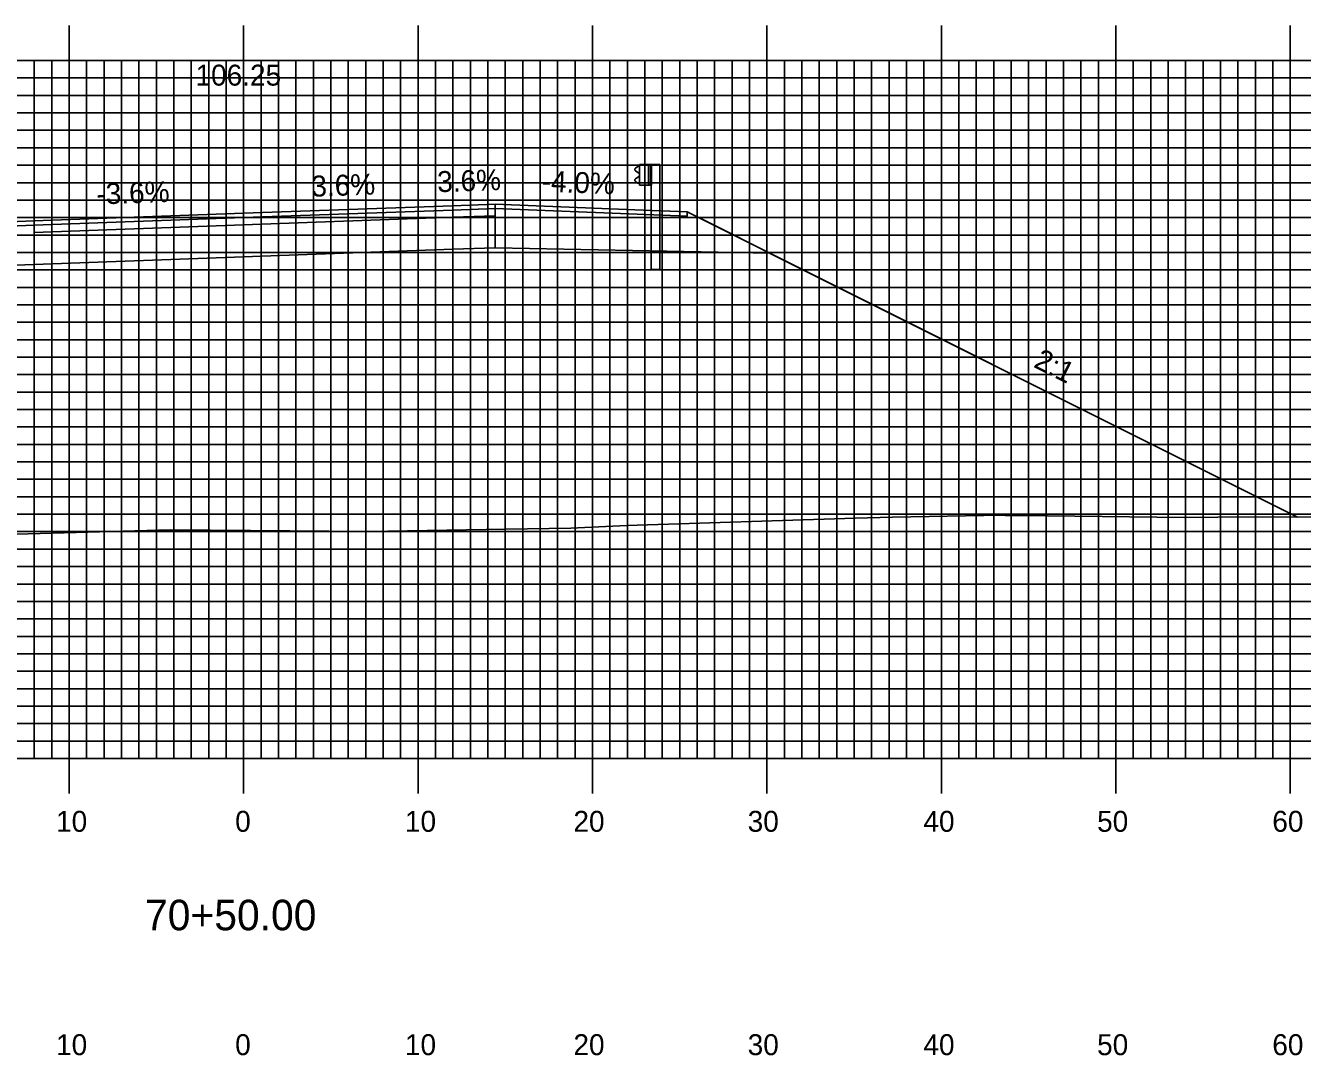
# Model space of a CAD drawing. Extents: x 1760217 to 1760560, y 442591 to 442811.
# Drawn here: x 1760370.2 to 1760443.4, y 442651.6 to 442710.7 of the extents above; entities that cross this region are included whole.
import ezdxf

# ---------------------------------------------------------------- set-up
doc = ezdxf.new("R2010")
doc.units = 0
for name, color, linetype in [('ANNOTATION', 7, 'Continuous'), ('D_Guardrail_Beam_Rt', 7, 'Continuous'), ('D_Roadway_Centerline', 7, 'Continuous'), ('D_Roadway_Centerline_Text', 7, 'Continuous'), ('D_Roadway_Edge_Shoulder', 7, 'Continuous'), ('D_Roadway_Edge_TW', 7, 'Continuous'), ('D_Roadway_Pavement', 7, 'Continuous'), ('D_Roadway_SlopeLines', 7, 'Continuous'), ('D_Roadway_SubGrade', 7, 'Continuous'), ('H_V ANNOTATION', 7, 'Continuous'), ('MAJOR', 7, 'Continuous'), ('MINOR', 7, 'Continuous'), ('S_Roadway_Centerline', 7, 'Continuous')]:
    doc.layers.add(name, color=color, linetype=linetype)

msp = doc.modelspace()

# ---------------------------------------------------------------- linework, layer by layer
at = {"layer": 'D_Guardrail_Beam_Rt'}
for p, q in [((1760405.308, 442702.592), (1760405.165, 442702.492)), ((1760405.165, 442702.349), (1760405.36, 442702.213)), ((1760405.36, 442702.014), (1760405.165, 442701.878)), ((1760405.398, 442702.613), (1760405.324, 442702.599)), ((1760405.394, 442702.148), (1760405.394, 442702.078)), ((1760405.398, 442702.697), (1760406.085, 442702.697)), ((1760405.398, 442701.53), (1760405.398, 442702.697)), ((1760405.919, 442702.697), (1760405.919, 442701.53)), ((1760406.023, 442702.697), (1760406.023, 442701.53)), ((1760406.085, 442702.697), (1760406.556, 442702.697)), ((1760406.085, 442702.697), (1760406.085, 442701.53)), ((1760406.556, 442702.697), (1760406.556, 442696.697)), ((1760405.165, 442701.734), (1760405.308, 442701.634)), ((1760405.324, 442701.628), (1760405.398, 442701.613)), ((1760406.085, 442701.53), (1760405.398, 442701.53)), ((1760406.065, 442696.697), (1760406.065, 442701.53)), ((1760406.065, 442696.697), (1760406.556, 442696.697))]:
    msp.add_line(p, q, dxfattribs=at)
for centre, major_axis, start_param, end_param in [((1760405.215, 442702.42), (-0.0877, 0), 5.323254, 7.243116), ((1760405.332, 442702.558), (-0.0417, 0), 4.907132, 5.323254), ((1760405.315, 442702.148), (0.0789, 0), 0, 0.959931), ((1760405.315, 442702.078), (0.0789, 0), 5.323254, 6.283185), ((1760405.215, 442701.806), (-0.0877, 0), 5.323254, 7.243116), ((1760405.332, 442701.668), (-0.0417, 0), 0.959931, 1.376053)]:
    msp.add_ellipse(centre, major_axis=major_axis, ratio=0.995501, start_param=start_param, end_param=end_param, dxfattribs=at)
at = {"layer": 'D_Roadway_Centerline'}
msp.add_lwpolyline([(1760323.215, 442680.799), (1760354.403, 442696.393), (1760354.408, 442696.395), (1760359.7, 442699.042), (1760362.701, 442699.162), (1760365.45, 442699.272), (1760370.698, 442699.482), (1760370.701, 442699.482), (1760382.693, 442699.914), (1760382.701, 442699.914), (1760394.698, 442700.346), (1760394.7, 442700.346), (1760397.126, 442700.433), (1760397.127, 442700.433), (1760405.126, 442700.113), (1760405.127, 442700.113), (1760408.127, 442699.993), (1760409.554, 442699.28), (1760412.877, 442697.618), (1760412.884, 442697.614), (1760443.11, 442682.502)], dxfattribs=at)
at = {"layer": 'D_Roadway_Edge_Shoulder'}
for points in [[(1760397.126, 442700.433), (1760405.127, 442700.113), (1760405.127, 442700.113), (1760408.127, 442699.993), (1760408.127, 442699.743), (1760397.126, 442700.183)], [(1760370.7, 442699.482), (1760362.701, 442699.162), (1760362.701, 442699.162), (1760359.7, 442699.042), (1760359.7, 442698.792), (1760370.7, 442699.232)]]:
    msp.add_lwpolyline(points, close=True, dxfattribs=at)
at = {"layer": 'D_Roadway_Edge_TW'}
for points in [[(1760370.7, 442699.232), (1760370.7, 442699.482), (1760382.701, 442699.914), (1760394.7, 442700.346), (1760394.7, 442700.096), (1760382.701, 442699.664)], [(1760394.7, 442700.346), (1760397.126, 442700.433), (1760397.126, 442700.183), (1760394.7, 442700.096)]]:
    msp.add_lwpolyline(points, close=True, dxfattribs=at)
at = {"layer": 'D_Roadway_Pavement'}
for points in [[(1760370.7, 442698.815), (1760370.7, 442699.232), (1760382.701, 442699.664), (1760394.7, 442700.096), (1760394.7, 442699.679), (1760382.701, 442699.247)], [(1760394.7, 442700.096), (1760397.126, 442700.183), (1760397.126, 442699.767), (1760394.7, 442699.679)]]:
    msp.add_lwpolyline(points, close=True, dxfattribs=at)
for points in [[(1760397.126, 442700.183), (1760397.126, 442699.767)], [(1760397.126, 442700.183), (1760397.126, 442699.767)], [(1760370.7, 442699.232), (1760370.7, 442698.815)]]:
    msp.add_lwpolyline(points, dxfattribs=at)
at = {"layer": 'D_Roadway_SlopeLines'}
msp.add_lwpolyline([(1760408.127, 442699.993), (1760443.11, 442682.502)], dxfattribs=at)
at = {"layer": 'D_Roadway_SubGrade'}
for points in [[(1760397.126, 442699.767), (1760397.126, 442700.183), (1760408.127, 442699.743), (1760408.127, 442699.993), (1760412.877, 442697.618), (1760397.126, 442697.933)], [(1760370.7, 442698.815), (1760370.7, 442699.232), (1760359.7, 442698.792), (1760359.7, 442699.042), (1760354.408, 442696.395), (1760370.7, 442696.982)], [(1760370.7, 442696.982), (1760370.7, 442698.815), (1760382.701, 442699.247), (1760394.7, 442699.679), (1760394.7, 442697.846), (1760382.701, 442697.414)], [(1760394.7, 442699.679), (1760397.126, 442699.767), (1760397.126, 442697.933), (1760394.7, 442697.846)]]:
    msp.add_lwpolyline(points, close=True, dxfattribs=at)
at = {"layer": 'MAJOR'}
for p, q in [((1760372.701, 442710.669), (1760372.701, 442708.665)), ((1760382.701, 442710.669), (1760382.701, 442708.665)), ((1760392.701, 442710.669), (1760392.701, 442708.665)), ((1760402.701, 442710.669), (1760402.701, 442708.665)), ((1760412.701, 442710.669), (1760412.701, 442708.665)), ((1760422.701, 442710.669), (1760422.701, 442708.665)), ((1760432.701, 442710.669), (1760432.701, 442708.665)), ((1760442.701, 442710.669), (1760442.701, 442708.665)), ((1760242.701, 442708.665), (1760522.701, 442708.665)), ((1760242.701, 442708.665), (1760522.701, 442708.665)), ((1760372.701, 442668.665), (1760372.701, 442708.665)), ((1760382.701, 442668.665), (1760382.701, 442708.665)), ((1760392.701, 442668.665), (1760392.701, 442708.665)), ((1760402.701, 442668.665), (1760402.701, 442708.665)), ((1760412.701, 442668.665), (1760412.701, 442708.665)), ((1760422.701, 442668.665), (1760422.701, 442708.665)), ((1760432.701, 442668.665), (1760432.701, 442708.665)), ((1760442.701, 442668.665), (1760442.701, 442708.665)), ((1760242.701, 442703.665), (1760522.701, 442703.665)), ((1760242.701, 442698.665), (1760522.701, 442698.665)), ((1760242.701, 442693.665), (1760522.701, 442693.665)), ((1760242.701, 442688.665), (1760522.701, 442688.665)), ((1760242.701, 442683.665), (1760522.701, 442683.665)), ((1760242.701, 442678.665), (1760522.701, 442678.665)), ((1760242.701, 442673.665), (1760522.701, 442673.665)), ((1760242.701, 442668.665), (1760522.701, 442668.665)), ((1760242.701, 442668.665), (1760522.701, 442668.665)), ((1760372.701, 442666.661), (1760372.701, 442668.665)), ((1760382.701, 442666.661), (1760382.701, 442668.665)), ((1760392.701, 442666.661), (1760392.701, 442668.665)), ((1760402.701, 442666.661), (1760402.701, 442668.665)), ((1760412.701, 442666.661), (1760412.701, 442668.665)), ((1760422.701, 442666.661), (1760422.701, 442668.665)), ((1760432.701, 442666.661), (1760432.701, 442668.665)), ((1760442.701, 442666.661), (1760442.701, 442668.665))]:
    msp.add_line(p, q, dxfattribs=at)
at = {"layer": 'MINOR'}
for p, q in [((1760370.701, 442668.665), (1760370.701, 442708.665)), ((1760371.701, 442668.665), (1760371.701, 442708.665)), ((1760373.701, 442668.665), (1760373.701, 442708.665)), ((1760374.701, 442668.665), (1760374.701, 442708.665)), ((1760375.701, 442668.665), (1760375.701, 442708.665)), ((1760376.701, 442668.665), (1760376.701, 442708.665)), ((1760377.701, 442668.665), (1760377.701, 442708.665)), ((1760378.701, 442668.665), (1760378.701, 442708.665)), ((1760379.701, 442668.665), (1760379.701, 442708.665)), ((1760380.701, 442668.665), (1760380.701, 442708.665)), ((1760381.701, 442668.665), (1760381.701, 442708.665)), ((1760383.701, 442668.665), (1760383.701, 442708.665)), ((1760384.701, 442668.665), (1760384.701, 442708.665)), ((1760385.701, 442668.665), (1760385.701, 442708.665)), ((1760386.701, 442668.665), (1760386.701, 442708.665)), ((1760387.701, 442668.665), (1760387.701, 442708.665)), ((1760388.701, 442668.665), (1760388.701, 442708.665)), ((1760389.701, 442668.665), (1760389.701, 442708.665)), ((1760390.701, 442668.665), (1760390.701, 442708.665)), ((1760391.701, 442668.665), (1760391.701, 442708.665)), ((1760393.701, 442668.665), (1760393.701, 442708.665)), ((1760394.701, 442668.665), (1760394.701, 442708.665)), ((1760395.701, 442668.665), (1760395.701, 442708.665)), ((1760396.701, 442668.665), (1760396.701, 442708.665)), ((1760397.701, 442668.665), (1760397.701, 442708.665)), ((1760398.701, 442668.665), (1760398.701, 442708.665)), ((1760399.701, 442668.665), (1760399.701, 442708.665)), ((1760400.701, 442668.665), (1760400.701, 442708.665)), ((1760401.701, 442668.665), (1760401.701, 442708.665)), ((1760403.701, 442668.665), (1760403.701, 442708.665)), ((1760404.701, 442668.665), (1760404.701, 442708.665)), ((1760405.701, 442668.665), (1760405.701, 442708.665)), ((1760406.701, 442668.665), (1760406.701, 442708.665)), ((1760407.701, 442668.665), (1760407.701, 442708.665)), ((1760408.701, 442668.665), (1760408.701, 442708.665)), ((1760409.701, 442668.665), (1760409.701, 442708.665)), ((1760410.701, 442668.665), (1760410.701, 442708.665)), ((1760411.701, 442668.665), (1760411.701, 442708.665)), ((1760413.701, 442668.665), (1760413.701, 442708.665)), ((1760414.701, 442668.665), (1760414.701, 442708.665)), ((1760415.701, 442668.665), (1760415.701, 442708.665)), ((1760416.701, 442668.665), (1760416.701, 442708.665)), ((1760417.701, 442668.665), (1760417.701, 442708.665)), ((1760418.701, 442668.665), (1760418.701, 442708.665)), ((1760419.701, 442668.665), (1760419.701, 442708.665)), ((1760420.701, 442668.665), (1760420.701, 442708.665)), ((1760421.701, 442668.665), (1760421.701, 442708.665)), ((1760423.701, 442668.665), (1760423.701, 442708.665)), ((1760424.701, 442668.665), (1760424.701, 442708.665)), ((1760425.701, 442668.665), (1760425.701, 442708.665)), ((1760426.701, 442668.665), (1760426.701, 442708.665)), ((1760427.701, 442668.665), (1760427.701, 442708.665)), ((1760428.701, 442668.665), (1760428.701, 442708.665)), ((1760429.701, 442668.665), (1760429.701, 442708.665)), ((1760430.701, 442668.665), (1760430.701, 442708.665)), ((1760431.701, 442668.665), (1760431.701, 442708.665)), ((1760433.701, 442668.665), (1760433.701, 442708.665)), ((1760434.701, 442668.665), (1760434.701, 442708.665)), ((1760435.701, 442668.665), (1760435.701, 442708.665)), ((1760436.701, 442668.665), (1760436.701, 442708.665)), ((1760437.701, 442668.665), (1760437.701, 442708.665)), ((1760438.701, 442668.665), (1760438.701, 442708.665)), ((1760439.701, 442668.665), (1760439.701, 442708.665)), ((1760440.701, 442668.665), (1760440.701, 442708.665)), ((1760441.701, 442668.665), (1760441.701, 442708.665)), ((1760242.701, 442707.665), (1760522.701, 442707.665)), ((1760242.701, 442706.665), (1760522.701, 442706.665)), ((1760242.701, 442705.665), (1760522.701, 442705.665)), ((1760242.701, 442704.665), (1760522.701, 442704.665)), ((1760242.701, 442702.665), (1760522.701, 442702.665)), ((1760242.701, 442701.665), (1760522.701, 442701.665)), ((1760242.701, 442700.665), (1760522.701, 442700.665)), ((1760242.701, 442699.665), (1760522.701, 442699.665)), ((1760242.701, 442697.665), (1760522.701, 442697.665)), ((1760242.701, 442696.665), (1760522.701, 442696.665)), ((1760242.701, 442695.665), (1760522.701, 442695.665)), ((1760242.701, 442694.665), (1760522.701, 442694.665)), ((1760242.701, 442692.665), (1760522.701, 442692.665)), ((1760242.701, 442691.665), (1760522.701, 442691.665)), ((1760242.701, 442690.665), (1760522.701, 442690.665)), ((1760242.701, 442689.665), (1760522.701, 442689.665)), ((1760242.701, 442687.665), (1760522.701, 442687.665)), ((1760242.701, 442686.665), (1760522.701, 442686.665)), ((1760242.701, 442685.665), (1760522.701, 442685.665)), ((1760242.701, 442684.665), (1760522.701, 442684.665)), ((1760242.701, 442682.665), (1760522.701, 442682.665)), ((1760242.701, 442681.665), (1760522.701, 442681.665)), ((1760242.701, 442680.665), (1760522.701, 442680.665)), ((1760242.701, 442679.665), (1760522.701, 442679.665)), ((1760242.701, 442677.665), (1760522.701, 442677.665)), ((1760242.701, 442676.665), (1760522.701, 442676.665)), ((1760242.701, 442675.665), (1760522.701, 442675.665)), ((1760242.701, 442674.665), (1760522.701, 442674.665)), ((1760242.701, 442672.665), (1760522.701, 442672.665)), ((1760242.701, 442671.665), (1760522.701, 442671.665)), ((1760242.701, 442670.665), (1760522.701, 442670.665)), ((1760242.701, 442669.665), (1760522.701, 442669.665))]:
    msp.add_line(p, q, dxfattribs=at)
at = {"layer": 'S_Roadway_Centerline'}
msp.add_lwpolyline([(1760298.086, 442679.835), (1760317.911, 442680.686), (1760322.979, 442680.798), (1760339.332, 442680.88), (1760343.353, 442681.019), (1760347.906, 442681.104), (1760354.978, 442681.333), (1760361.271, 442681.352), (1760366.901, 442681.451), (1760373.111, 442681.617), (1760378.494, 442681.772), (1760383.101, 442681.734), (1760389.841, 442681.682), (1760397.736, 442681.811), (1760401.457, 442681.863), (1760404.672, 442682.017), (1760417.761, 442682.433), (1760419.894, 442682.504), (1760426.19, 442682.617), (1760426.367, 442682.586), (1760427.218, 442682.585), (1760436.615, 442682.478), (1760438.559, 442682.495), (1760447.953, 442682.51)], dxfattribs=at)

# ---------------------------------------------------------------- texts
at = {"layer": 'ANNOTATION'}
for s, rotation, p in [('3.6%', 2.06182, (1760386.606, 442700.856)), ('3.6%', 2.05364, (1760393.82, 442701.116)), ('-4.0%', 357.70957, (1760399.771, 442701.163)), ('-3.6%', 2.06169, (1760374.283, 442700.413)), ('2:1', 333.43553, (1760427.931, 442691.127))]:
    msp.add_text(s, height=1.2, rotation=rotation, dxfattribs=at).set_placement(p)
at = {"layer": 'D_Roadway_Centerline'}
for s, p in [('C', (1760382.696, 442699.914)), ('L', (1760382.701, 442699.907))]:
    msp.add_text(s, height=0.0146, dxfattribs=at).set_placement(p)
at = {"layer": 'D_Roadway_Centerline_Text'}
msp.add_text('106.25', height=1.2, dxfattribs=at).set_placement((1760379.945, 442707.227))
at = {"layer": 'H_V ANNOTATION'}
for s, height, p in [('10', 1.2, (1760371.951, 442664.465)), ('0', 1.2, (1760382.219, 442664.465)), ('10', 1.2, (1760391.951, 442664.465)), ('20', 1.2, (1760401.609, 442664.465)), ('30', 1.2, (1760411.598, 442664.465)), ('40', 1.2, (1760421.673, 442664.465)), ('50', 1.2, (1760431.63, 442664.465)), ('60', 1.2, (1760441.673, 442664.465)), ('70+50.00', 1.75, (1760377.051, 442658.821)), ('10', 1.2, (1760371.951, 442651.665)), ('0', 1.2, (1760382.219, 442651.665)), ('10', 1.2, (1760391.951, 442651.665)), ('20', 1.2, (1760401.609, 442651.665)), ('30', 1.2, (1760411.598, 442651.665)), ('40', 1.2, (1760421.673, 442651.665)), ('50', 1.2, (1760431.63, 442651.665)), ('60', 1.2, (1760441.673, 442651.665))]:
    msp.add_text(s, height=height, dxfattribs=at).set_placement(p)

doc.saveas('drawing.dxf')
